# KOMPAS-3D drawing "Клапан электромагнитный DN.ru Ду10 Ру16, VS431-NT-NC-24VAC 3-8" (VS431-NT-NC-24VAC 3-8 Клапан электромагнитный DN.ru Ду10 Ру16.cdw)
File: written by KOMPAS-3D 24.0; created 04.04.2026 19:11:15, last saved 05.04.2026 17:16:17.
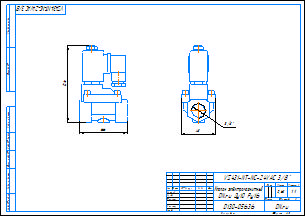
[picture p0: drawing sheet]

Document properties: c3d_UniqueCompID: ef56311e-7521-43dc-8291-0e6108b3d81d; Обозначение: VS400-ET-NC-220VAC 3-8; Наименование: Клапан электромагнитный DN.ru Ду10 Ру16; Автор: artio; Класс точности: c; Знак неуказанной шероховатости: Шероховатость не задана; Рассекать на разрезах: Да; Автор: artio; Форматы листов документа: A3; Полное имя файла: VS431-NT-NC-24VAC 3-8 Клапан электромагнитный DN.ru Ду10 Ру16.m3d; Масса: 0.62; Наименование: Клапан электромагнитный DN.ru Ду10 Ру16; Количество листов документа: 1; Примечание: D130-05636

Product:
- Body: Тело 1  | qty 1
    Масса: 1.030062
- Part/product: Клапан электромагнитный DN.ru Ду10 Ру16  | designation VS431-NT-NC-24VAC 3-8
    Масса: 0.62
    Раздел спецификации: Прочие изделия
    Примечание: D130-05636
    additional columns: ef56311e-7521-43dc-8291-0e6108b3d81d; VS400-ET-NC-220VAC 3-8; artio; c; Шероховатость не задана; Да

Views: Вид 1, Спереди, Проекционный вид 2
Referenced files in C:\Users\artio\OneDrive\Рабочий стол\Клапан электромагнитный DN.ru\VS400-ET-NC\VS400-ET-NC-24VDC\: VS400-ET-NC-24VDC 3-8 Клапан электромагнитный DN.ru Ду10 Ру16.m3d
Referenced files in C:\Users\artio\OneDrive\Рабочий стол\Клапан электромагнитный DN.ru\VS431\VS431-NT-NC\VS431-NT-NC-24VAC\Ду10\: VS431-NT-NC-24VAC 3-8 Клапан электромагнитный DN.ru Ду10 Ру16.m3d
Referenced files in C:\Users\artio\OneDrive\Рабочий стол\Клапан электромагнитный DN.ru\VS400-ET-NC\: VS400-ET-NC-24VDC 3-8 Клапан электромагнитный DN.ru Ду10 Ру16.cdw
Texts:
  VS431-NT-NC-24VAC 3-8
  Клапан электромагнитный
  DN.ru Ду10 Ру16
  VS431-NT-NC-24VAC 3/8"
  VS431-NT-NC-24VAC 3/8"-
  Клапан электромагнитный DN.ru Ду10 Ру16
  VS431-NT-NC-24VAC 3-8 Клапан электромагнитный DN.ru Ду10 Ру16
Dimensions and other numbers on the sheet: 0; 3; 2; 4; 48; 3/8"; 66; 106; 1:1; 1; 0,62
